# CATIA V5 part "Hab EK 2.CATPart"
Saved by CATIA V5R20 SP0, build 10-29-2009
Part number: Hab EK
Bounding box of the stored display mesh (mm): x 10 to 20, y 201.525 to 350.66, z -437.358 to 13.708
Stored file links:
  D:\Dropbox\IAO_2012\IAO_2012_766_vlaroche\vlaroche\vlaroche\IAO\A rendre\Hab EK 2.CATPart
  U:\IAO\IAO\IAO\A rendre\Assemblage.CATProduct
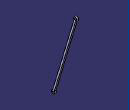
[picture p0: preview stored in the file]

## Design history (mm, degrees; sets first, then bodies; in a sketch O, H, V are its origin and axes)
Set1
  Point1: linked copy from another document
  Point2: linked copy from another document
Body1 (main body)
  Sketch1 on yz-plane, origin (0, 0, 0), H (0, 1, 0), V (0, 0, 1)
    point P1 (211.517, -427.3593)
    arc A1 centre (211.517, -427.3593) radius 10 from (218.7922, -420.4984) to (209.2129, -417.6284) cw
    point P2 (218.7922, -420.4984)
    point P3 (209.2129, -417.6284)
    reference projected point E1 (211.517, -427.3593) from Point1
    circle A2 centre (340.6677, 3.7093) radius 5
    circle A3 centre (211.517, -427.3593) radius 5
    construction line L1 (378.0073, 128.3384) -> (318.8141, -69.2318)
    line L2 (342.9718, -6.0216) -> (218.7922, -420.4984)
    line L3 (209.2129, -417.6284) -> (333.3925, -3.1516)
    point P8 (218.7922, -420.4984)
    point P9 (209.2129, -417.6284)
    arc A4 centre (340.6677, 3.7093) radius 10 from (333.3925, -3.1516) to (342.9718, -6.0216) cw
    point P11 (340.6677, 3.7093)
    point P12 (337.7977, -5.87)
    reference projected point E2 (340.6677, 3.7093) from Point2
    axis line L4 (222.0704, -392.135) -> (211.3549, -427.9005)
    reference projected point E3 (340.6677, 3.7093) from Point2
    reference projected point E4 (211.517, -427.3593) from Point1
    radius A2 = 5
    radius A3 = 5
    distance L1 L2 = 5
    radius A4 = 10
    radius A1 = 10
    coincidence: P1 E1, A4 P12, P12 L1, P11 E2, P8 P2, P3 P9, E4 L4
    symmetry: L3 L2 L1, L3 L2 L4
    equidistance: L3 L2 E3
  Pad1: profile Sketch1, direction (1, 0, 0), length 10, opposite side length -20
